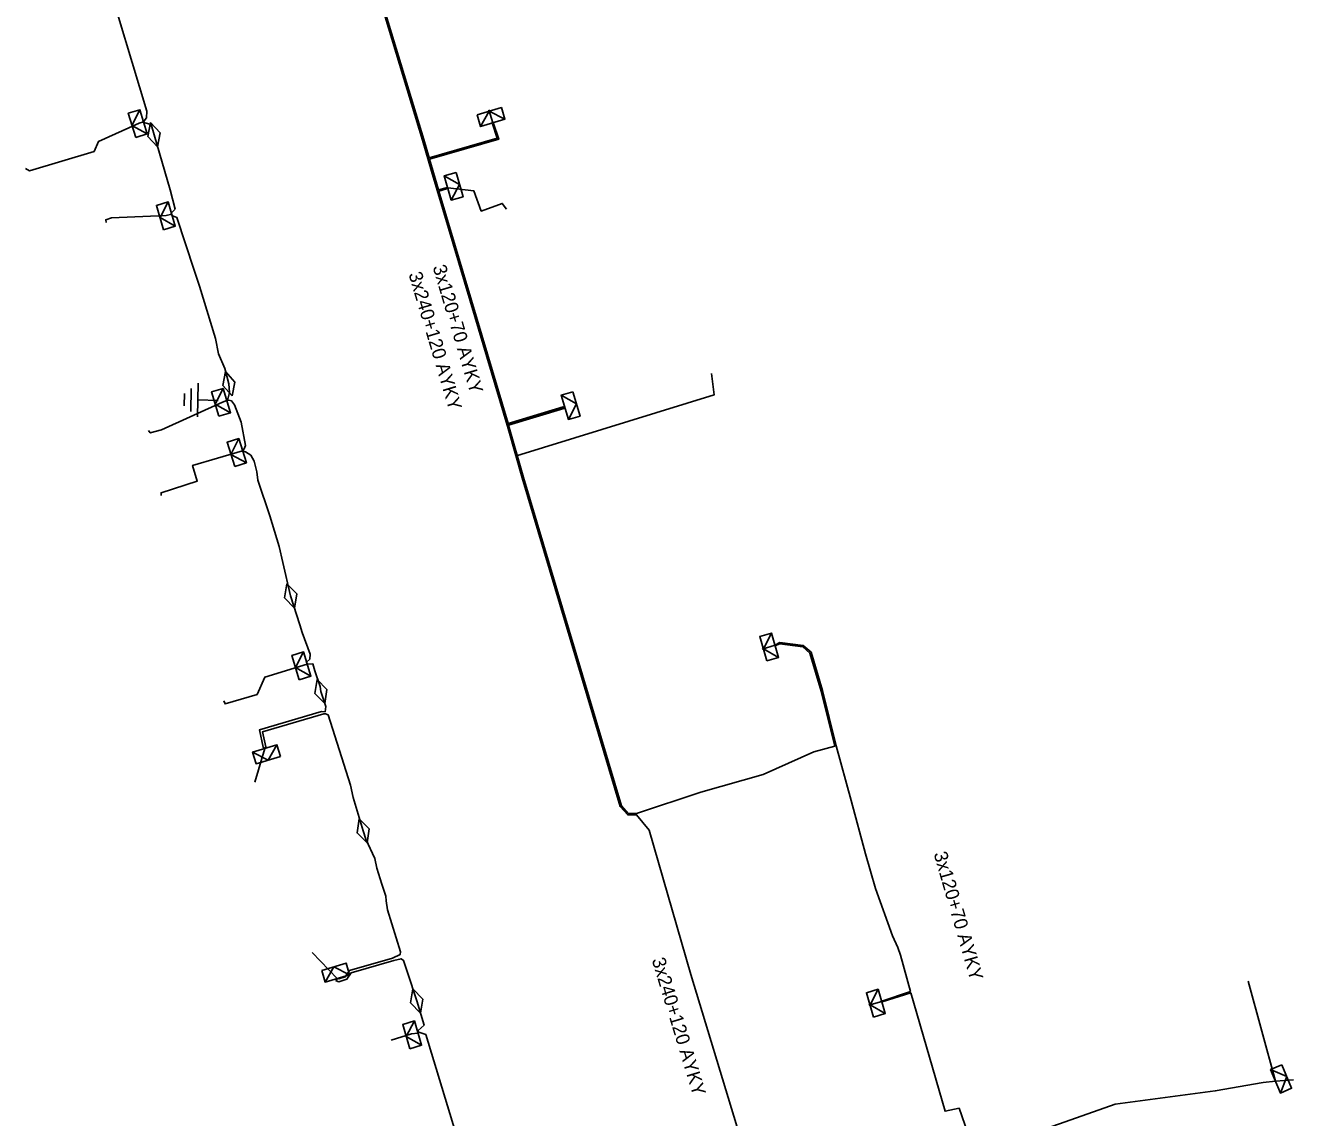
# Model space of a CAD drawing. Extents: x -540028 to -538776, y -1157064 to -1155670.
# Drawn here: x -539698.7 to -539604.9, y -1156059.8 to -1155979.1 of the extents above; entities that cross this region are included whole.
import ezdxf

# ---------------------------------------------------------------- set-up
doc = ezdxf.new("R2010")
doc.units = 0
for name, color, linetype in [('Vrstva 15', 7, 'Continuous'), ('Vrstva 19', 7, 'Continuous'), ('Vrstva 2', 7, 'Continuous'), ('Vrstva 31', 7, 'Continuous'), ('Vrstva 5', 7, 'Continuous'), ('Vrstva 52', 7, 'Continuous'), ('Vrstva 59', 7, 'Continuous'), ('Vrstva 6', 7, 'Continuous')]:
    doc.layers.add(name, color=color, linetype=linetype)

# ---------------------------------------------------------------- blocks, each defined once
blk = doc.blocks.new('17')
at = {"layer": 'Vrstva 2'}
blk.add_lwpolyline([(-1.875, 0), (0, 0.9375), (1.875, 0), (0, -0.9375)], close=True, dxfattribs=at)
blk = doc.blocks.new('23')
at = {"layer": 'Vrstva 2'}
blk.add_lwpolyline([(1.875, -1.8), (-1.875, -1.8), (-1.875, 0), (1.875, 0)], close=True, dxfattribs=at)
blk.add_lwpolyline([(1.875, 0), (0, -1.8), (-1.875, 0)], dxfattribs=at)
blk = doc.blocks.new('11')
at = {"layer": 'Vrstva 2'}
for p, q in [((0, -4.3), (0, -1.3)), ((-2.5, -4.3), (2.5, -4.3)), ((-1.7, -5.3), (1.7, -5.3)), ((-0.9, -6.3), (0.9, -6.3))]:
    blk.add_line(p, q, dxfattribs=at)

msp = doc.modelspace()

# ---------------------------------------------------------------- linework, layer by layer
at = {"layer": 'Vrstva 5'}
for points in [[(-539689.41, -1155986.37), (-539689.89, -1155986.25), (-539689.973, -1155986.183), (-539689.93, -1155986.1), (-539689.75, -1155985.89), (-539689.74, -1155985.4), (-539692.91, -1155974.83)], [(-539633.673, -1156082.436), (-539633.351, -1156083.51), (-539637.618, -1156085.299), (-539638.171, -1156085.351), (-539638.491, -1156085.164), (-539640.007, -1156080.996), (-539641.448, -1156076.483), (-539641.898, -1156074.555), (-539642.918, -1156071.984), (-539643.249, -1156070.189), (-539643.579, -1156068.192), (-539644.69, -1156064.44), (-539646.1, -1156060.45), (-539649.52, -1156049.19), (-539652.595, -1156038.504), (-539653.523, -1156037.39), (-539654.183, -1156037.39), (-539654.735, -1156036.755), (-539661.988, -1156012.494), (-539663.018, -1156008.834), (-539665.828, -1155999.414), (-539668.678, -1155989.834), (-539669.358, -1155987.524), (-539672.428, -1155977.354)], [(-539672.227, -1155977.677), (-539669.262, -1155987.496), (-539668.863, -1155988.851), (-539663.842, -1155987.396), (-539664.182, -1155986.338), (-539664.156, -1155986.262), (-539664.092, -1155986.316), (-539663.718, -1155987.464), (-539668.835, -1155988.947), (-539668.162, -1155991.203), (-539667.608, -1155991.062), (-539667.481, -1155991.064)], [(-539666.92, -1156060.82), (-539669.11, -1156053.62), (-539669.63, -1156053.45), (-539669.686, -1156053.512), (-539669.66, -1156053.31), (-539669.23, -1156052.92), (-539669.78, -1156051.13), (-539670.45, -1156049.03), (-539670.76, -1156048.14), (-539670.94, -1156048.02), (-539671.46, -1156048.148), (-539674.625, -1156049.048), (-539674.939, -1156049.532), (-539675.532, -1156049.713), (-539675.742, -1156049.647), (-539675.65, -1156049.468), (-539675.532, -1156049.504), (-539675.067, -1156049.362), (-539674.751, -1156048.876), (-539671.578, -1156047.974), (-539671.01, -1156047.71), (-539670.97, -1156047.51), (-539671.93, -1156044.39), (-539672.03, -1156043.73), (-539672.07, -1156043.4), (-539672.36, -1156042.5), (-539672.72, -1156041.33), (-539672.87, -1156040.62), (-539673.54, -1156039.18), (-539673.74, -1156038.57), (-539674.48, -1156036.11), (-539674.68, -1156035.19), (-539676.33, -1156030), (-539676.53, -1156029.91), (-539676.647, -1156029.908), (-539681.18, -1156031.239), (-539680.94, -1156032.35), (-539681.016, -1156032.472), (-539681.135, -1156032.394), (-539681.414, -1156031.103), (-539676.819, -1156029.754), (-539676.56, -1156029.76), (-539676.51, -1156029.37), (-539676.86, -1156028.27), (-539676.92, -1156027.89), (-539677.31, -1156026.74), (-539677.45, -1156026.23), (-539677.833, -1156026.257), (-539677.874, -1156026.239), (-539677.93, -1156026.11), (-539677.69, -1156025.88), (-539677.65, -1156025.5), (-539678.25, -1156023.9), (-539678.41, -1156023.34), (-539679.1, -1156021.21), (-539679.68, -1156018.74), (-539679.95, -1156017.56), (-539680.64, -1156015.3), (-539681.52, -1156012.66), (-539681.59, -1156012.04), (-539681.79, -1156011.26), (-539682.05, -1156010.82), (-539682.444, -1156010.561), (-539682.653, -1156010.48), (-539682.54, -1156010.33), (-539682.43, -1156010.1), (-539682.77, -1156008.36), (-539683.25, -1156007.1), (-539683.47, -1156006.8), (-539683.68, -1156006.74), (-539683.812, -1156006.773), (-539683.73, -1156006.57), (-539683.61, -1156006.17), (-539683.67, -1156005.53), (-539683.97, -1156004.41), (-539684.43, -1156003.33), (-539684.66, -1156002.19), (-539685.84, -1155998.32), (-539686.23, -1155997.15), (-539687.52, -1155993.24), (-539687.88, -1155993.11), (-539687.891, -1155993.002), (-539687.93, -1155992.94), (-539687.64, -1155992.64), (-539688.01, -1155991.2), (-539689.2, -1155987.13), (-539689.41, -1155986.37)], [(-539667.481, -1155991.064), (-539667.586, -1155991.135), (-539668.137, -1155991.3), (-539665.732, -1155999.386), (-539663.013, -1156008.475), (-539658.949, -1156007.243), (-539658.829, -1156007.273)], [(-539658.829, -1156007.273), (-539658.891, -1156007.366), (-539662.989, -1156008.584), (-539661.892, -1156012.465), (-539654.645, -1156036.706), (-539654.137, -1156037.29), (-539653.523, -1156037.29), (-539648.78, -1156035.7), (-539644.16, -1156034.39), (-539640.41, -1156032.72), (-539638.869, -1156032.302), (-539639.878, -1156028.233), (-539640.704, -1156025.428), (-539641.241, -1156024.968), (-539642.926, -1156024.751), (-539643.251, -1156024.865), (-539643.289, -1156024.856), (-539643.264, -1156024.82), (-539642.934, -1156024.649), (-539641.199, -1156024.872), (-539640.616, -1156025.372), (-539639.782, -1156028.207), (-539638.771, -1156032.278), (-539637.65, -1156036.32), (-539636.6, -1156040.27), (-539635.87, -1156042.83), (-539634.61, -1156046.32), (-539634.208, -1156047.19), (-539634, -1156047.76), (-539633.284, -1156050.442), (-539635.384, -1156051.142), (-539635.402, -1156051.172), (-539635.372, -1156051.19), (-539633.255, -1156050.537), (-539630.72, -1156059.28), (-539629.68, -1156059.06), (-539628.6, -1156062.19)]]:
    msp.add_lwpolyline(points, dxfattribs=at)
at = {"layer": 'Vrstva 52'}
for points in [[(-539689.973, -1155986.183), (-539690.3, -1155986.27), (-539693.308, -1155987.644), (-539693.629, -1155988.382), (-539698.407, -1155989.795), (-539698.713, -1155989.636)], [(-539667.481, -1155991.064), (-539665.55, -1155991.29), (-539665.01, -1155992.78), (-539663.45, -1155992.21), (-539663.147, -1155992.628)], [(-539687.891, -1155993.002), (-539688.3, -1155993.09), (-539692.341, -1155993.286), (-539692.773, -1155993.416), (-539692.738, -1155993.615)], [(-539658.829, -1156007.273), (-539663.051, -1156008.549), (-539662.395, -1156010.863), (-539647.79, -1156006.36), (-539647.974, -1156004.781)], [(-539683.812, -1156006.773), (-539684.14, -1156006.89), (-539688.655, -1156008.935), (-539689.474, -1156009.169), (-539689.603, -1156008.998)], [(-539682.653, -1156010.48), (-539686.352, -1156011.562), (-539686.006, -1156012.73), (-539688.684, -1156013.586), (-539688.661, -1156013.789)], [(-539677.874, -1156026.239), (-539681.005, -1156027.205), (-539681.583, -1156028.486), (-539683.948, -1156029.185), (-539684.038, -1156028.962)], [(-539669.686, -1156053.512), (-539670.17, -1156053.56), (-539671.674, -1156054.026)], [(-539627.08, -1156064.21), (-539627.65, -1156063.01), (-539627.84, -1156062.39), (-539626.96, -1156061.87), (-539621.43, -1156059.92), (-539618.13, -1156058.76), (-539610.74, -1156057.78), (-539607.21, -1156057.16), (-539606.29, -1156057.07)]]:
    msp.add_lwpolyline(points, dxfattribs=at)
at = {"layer": 'Vrstva 59'}
for points in [[(-539664.156, -1155986.262), (-539664.439, -1155985.303)], [(-539643.289, -1156024.856), (-539644.248, -1156025.137)], [(-539681.016, -1156032.472), (-539681.753, -1156034.977)], [(-539675.65, -1156049.468), (-539677.509, -1156047.542)], [(-539606.29, -1156057.07), (-539608.302, -1156049.663)], [(-539635.402, -1156051.172), (-539636.361, -1156051.453)], [(-539606.29, -1156057.07), (-539604.947, -1156056.968)]]:
    msp.add_lwpolyline(points, dxfattribs=at)

# ---------------------------------------------------------------- block references
at = {"layer": 'Vrstva 15', "xscale": 0.5000000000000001, "yscale": 0.5, "rotation": -91.07315280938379}
msp.add_blockref('11', (-539683.812, -1156006.773), dxfattribs=at)
at = {"layer": 'Vrstva 19'}
for p, xscale, yscale, rotation in [((-539689.2, -1155987.13), 0.5000000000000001, 0.5, -73.70196198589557), ((-539683.67, -1156005.53), 0.5, 0.5, 104.99507918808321), ((-539679.1, -1156021.21), 0.5000000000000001, 0.5, -72.050596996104), ((-539676.86, -1156028.27), 0.5000000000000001, 0.5, -72.34987580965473), ((-539673.74, -1156038.57), 0.5, 0.5000000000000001, -71.84729410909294), ((-539669.78, -1156051.13), 0.5, 0.5, -72.91976640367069)]:
    msp.add_blockref('17', p, dxfattribs=dict(at, xscale=xscale, yscale=yscale, rotation=rotation))
at = {"layer": 'Vrstva 31'}
for p, xscale, yscale, rotation in [((-539689.973, -1155986.183), 0.5, 0.5, -72.88118612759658), ((-539664.156, -1155986.262), 0.49999999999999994, 0.5000000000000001, -163.54772773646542), ((-539667.481, -1155991.064), 0.49999999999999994, 0.5, 105.98815836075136), ((-539687.891, -1155993.002), 0.5000000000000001, 0.4999999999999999, -73.6370639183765), ((-539683.812, -1156006.773), 0.5000000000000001, 0.5, -73.29221943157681), ((-539658.829, -1156007.273), 0.49999999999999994, 0.5000000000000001, 106.42539441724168), ((-539682.653, -1156010.48), 0.5, 0.5, -72.45916664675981), ((-539643.289, -1156024.856), 0.5, 0.5, -73.66221113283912), ((-539677.874, -1156026.239), 0.5, 0.5000000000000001, -72.89460278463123), ((-539681.016, -1156032.472), 0.5, 0.5, 16.78603046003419), ((-539675.65, -1156049.468), 0.5, 0.5000000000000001, -163.4643360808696), ((-539635.402, -1156051.172), 0.5000000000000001, 0.4999999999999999, -73.65599998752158), ((-539669.686, -1156053.512), 0.5, 0.49999999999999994, -73.45766392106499), ((-539606.29, -1156057.07), 0.5, 0.5, 112.77350848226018)]:
    msp.add_blockref('23', p, dxfattribs=dict(at, xscale=xscale, yscale=yscale, rotation=rotation))

# ---------------------------------------------------------------- texts
at = {"layer": 'Vrstva 6'}
for s, rotation, p in [('3x120+70 AYKY', 286.564, (-539668.609, -1155996.902)), ('3x240+120 AYKY', 286.567, (-539670.394, -1155997.42)), ('3x120+70 AYKY', 286.169, (-539631.571, -1156040.249)), ('3x240+120 AYKY', 286.895, (-539652.411, -1156048.089))]:
    msp.add_text(s, height=1, rotation=rotation, dxfattribs=at).set_placement(p)

doc.saveas('drawing.dxf')
